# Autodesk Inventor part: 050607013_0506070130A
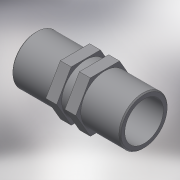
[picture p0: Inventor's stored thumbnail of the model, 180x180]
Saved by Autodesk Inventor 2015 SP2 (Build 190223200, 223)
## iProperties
Created: 2017-05
Part Number: 050607013_0506070130A
Material: Generic
Description: PLASSON NIPPLE 1.1/4"-1.1/4"
Document SubType Name: Modeling
Designer: KIM
Density: 1 g/cm^3
Appearance: Default
Author: KIM
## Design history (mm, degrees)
derived "050607.ipt"
feature "Solid1::050607.ipt"
tag "TaggingFeature1"
body "Solid1"
other parameters: "d1" = 41.91, "d2" = 46, "d3" = 33.528, "d4" = 22, "d5" = 22, "d6" = 6, "d8" = 0.6, "d12" = 0, "R_" = 41.91, "E_" = 46, "l_2" = 22
